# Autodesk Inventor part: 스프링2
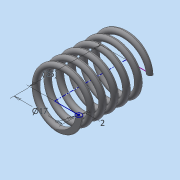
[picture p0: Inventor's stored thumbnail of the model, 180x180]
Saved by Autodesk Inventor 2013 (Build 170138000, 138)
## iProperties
Created: 2019-07
Part Number: 스프링2
Material: 일반
Document SubType Name: Modeling
Designer: dgall
Density: 1 g/cm^3
Mass: 0.980803 g
Surface Area: 19.9894 cm^2
Volume: 0.980803 cm^3
Author: dgall
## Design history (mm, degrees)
sketch "스케치1"
  geometry: L1 (8.5, 0)-(0, 0); L2 (0, 0)-(0, 16); L3 (0, 16)-(8.5, 16); C1 r 1 at (8.5, 0)
  constraints: 6 end point, 2 parallel, 1 centre point, 1 coincident, 1 horizontal, 1 perpendicular
  dimensions: "d0" = 17 diameter of L1.start L2; "d2" = 16 distance of L1.end L2.end (derived); "d3" = 2 diameter of C1
feature "코일1" pitch "d4" = 10; turns "d6" = 6; dims "d5" = 16 (= d2), "d7" = 0, angle "d8" = 90 deg, angle "d9" = 90 deg, "d10" = 0, "d11" = 0
node "작업 평면1"
feature "분할1"
feature "분할2"
node "솔리드1"
